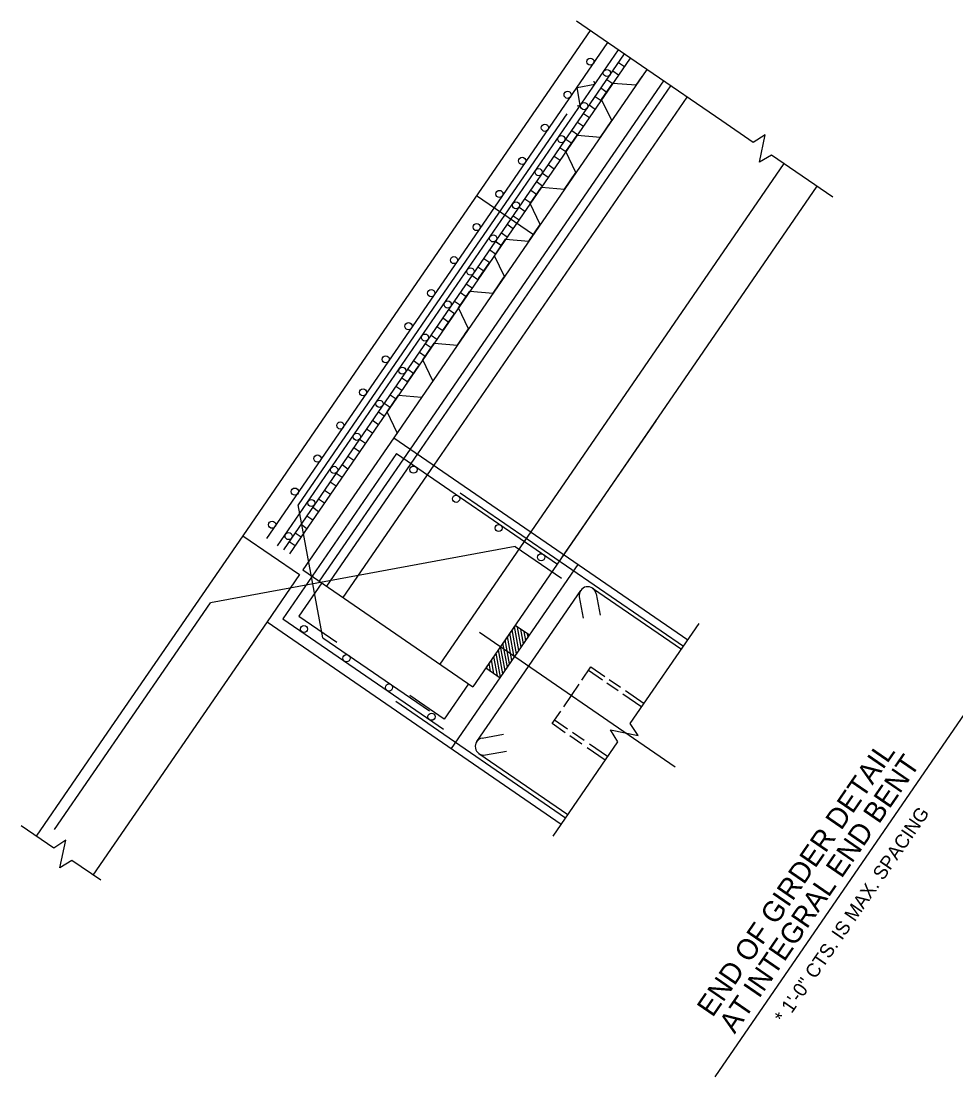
# Model space of a CAD drawing. Extents: x 2381318.4 to 2381387.3, y 332431.1 to 332503.2.
# Drawn here: x 2381332.66 to 2381346.24, y 332455.04 to 332470.39 of the extents above; entities that cross this region are included whole.
import ezdxf

# ---------------------------------------------------------------- set-up
doc = ezdxf.new("R2010")
doc.units = 0
for name, color, linetype in [('Beam Bolsters CELL', 7, 'Continuous'), ('Dimension Lines', 7, 'Continuous'), ('Dimension_Lines', 7, 'Continuous'), ('Mis Object Lines', 7, 'Continuous'), ('P_SMU_Approach_Slab', 7, 'Continuous'), ('P_SMU_BBU', 7, 'Continuous'), ('P_SMU_Deck', 7, 'Continuous'), ('P_SMU_Elastomeric Bearings', 7, 'Continuous'), ('P_SMU_End_Bent_Cap', 7, 'Continuous'), ('P_SMU_Mis_Centerline_Manual', 7, 'Continuous'), ('P_SMU_Rebar_B_Bar', 7, 'Continuous'), ('P_SMU_SIP_Metal_Formwork', 7, 'Continuous'), ('P_SMU_Steel_Pile', 7, 'Continuous'), ('Rebar Lines', 7, 'Continuous'), ('Rebar Lines CELL', 7, 'Continuous'), ('Structural Steel Lines', 7, 'Continuous'), ('Subtitle Text', 7, 'Continuous'), ('Sup Concrete Girder Lines', 7, 'Continuous'), ('Text', 7, 'Continuous')]:
    doc.layers.add(name, color=color, linetype=linetype)

msp = doc.modelspace()

# ---------------------------------------------------------------- linework, layer by layer
at = {"layer": 'Beam Bolsters CELL'}
msp.add_lwpolyline([(2381340.74, 332469.154), (2381340.785, 332469.163), (2381340.737, 332469.423), (2381340.996, 332469.47), (2381340.987, 332469.516)], dxfattribs=at)
at = {"layer": 'Dimension Lines'}
msp.add_line((2381341.882, 332464.577), (2381340.518, 332462.592), dxfattribs=at)
at = {"layer": 'Dimension_Lines'}
for p, q in [((2381341.752, 332469.684), (2381340.729, 332470.387)), ((2381342.839, 332468.936), (2381341.752, 332469.684)), ((2381343.298, 332468.621), (2381342.839, 332468.936)), ((2381343.473, 332468.735), (2381343.298, 332468.621)), ((2381343.39, 332468.334), (2381343.473, 332468.735)), ((2381343.564, 332468.438), (2381343.39, 332468.334)), ((2381344.453, 332467.828), (2381343.564, 332468.438)), ((2381341.511, 332460.175), (2381342.51, 332461.628)), ((2381341.329, 332459.909), (2381341.225, 332460.083)), ((2381341.225, 332460.083), (2381341.625, 332460)), ((2381341.625, 332460), (2381341.511, 332460.175)), ((2381340.388, 332458.54), (2381341.329, 332459.909)), ((2381333.132, 332458.366), (2381332.659, 332458.691)), ((2381333.307, 332458.48), (2381333.132, 332458.366)), ((2381333.223, 332458.079), (2381333.307, 332458.48)), ((2381333.397, 332458.183), (2381333.223, 332458.079)), ((2381333.815, 332457.897), (2381333.397, 332458.183))]:
    msp.add_line(p, q, dxfattribs=at)
at = {"layer": 'Mis Object Lines'}
msp.add_line((2381338.072, 332464.332), (2381338.073, 332464.331), dxfattribs=at)
at = {"layer": 'P_SMU_Approach_Slab'}
for p, q in [((2381335.879, 332462.906), (2381333.916, 332460.049)), ((2381336.232, 332461.653), (2381333.703, 332457.973)), ((2381333.916, 332460.049), (2381332.879, 332458.54))]:
    msp.add_line(p, q, dxfattribs=at)
at = {"layer": 'P_SMU_BBU'}
for p, q in [((2381341.424, 332469.909), (2381336.472, 332462.701)), ((2381341.51, 332469.85), (2381336.558, 332462.642)), ((2381341.341, 332469.787), (2381341.427, 332469.728)), ((2381341.256, 332469.663), (2381341.341, 332469.604)), ((2381341.085, 332469.415), (2381341.171, 332469.356)), ((2381341.095, 332469.246), (2381341.259, 332469.485)), ((2381341.17, 332469.539), (2381341.256, 332469.48)), ((2381341, 332469.291), (2381341.086, 332469.232)), ((2381340.915, 332469.168), (2381341.001, 332469.109)), ((2381340.83, 332469.044), (2381340.916, 332468.985)), ((2381340.66, 332468.796), (2381340.746, 332468.737)), ((2381340.745, 332468.92), (2381340.831, 332468.861)), ((2381340.575, 332468.672), (2381340.66, 332468.613)), ((2381340.576, 332468.489), (2381340.74, 332468.728)), ((2381340.489, 332468.548), (2381340.575, 332468.489)), ((2381340.404, 332468.424), (2381340.49, 332468.365)), ((2381340.319, 332468.3), (2381340.405, 332468.241)), ((2381340.149, 332468.053), (2381340.235, 332467.994)), ((2381340.234, 332468.177), (2381340.32, 332468.118)), ((2381340.056, 332467.733), (2381340.22, 332467.972)), ((2381340.064, 332467.929), (2381340.15, 332467.87)), ((2381339.979, 332467.805), (2381340.065, 332467.746)), ((2381339.894, 332467.681), (2381339.979, 332467.622)), ((2381339.723, 332467.433), (2381339.809, 332467.374)), ((2381339.808, 332467.557), (2381339.894, 332467.498)), ((2381339.638, 332467.309), (2381339.724, 332467.25)), ((2381339.536, 332466.977), (2381339.7, 332467.216)), ((2381339.553, 332467.186), (2381339.639, 332467.127)), ((2381339.553, 332467.185), (2381339.639, 332467.126)), ((2381339.468, 332467.062), (2381339.554, 332467.003)), ((2381339.468, 332467.062), (2381339.554, 332467.003)), ((2381339.298, 332466.814), (2381339.383, 332466.755)), ((2381339.307, 332466.644), (2381339.472, 332466.883)), ((2381339.383, 332466.938), (2381339.469, 332466.879)), ((2381339.212, 332466.69), (2381339.298, 332466.631)), ((2381339.127, 332466.566), (2381339.213, 332466.507)), ((2381339.016, 332466.22), (2381339.181, 332466.459)), ((2381339.042, 332466.442), (2381339.128, 332466.383)), ((2381338.872, 332466.194), (2381338.958, 332466.135)), ((2381338.957, 332466.318), (2381339.043, 332466.259)), ((2381338.787, 332466.071), (2381338.873, 332466.012)), ((2381338.788, 332465.888), (2381338.952, 332466.127)), ((2381338.702, 332465.947), (2381338.788, 332465.888)), ((2381338.617, 332465.823), (2381338.702, 332465.764)), ((2381338.446, 332465.575), (2381338.532, 332465.516)), ((2381338.497, 332465.464), (2381338.661, 332465.703)), ((2381338.532, 332465.699), (2381338.617, 332465.64)), ((2381338.361, 332465.451), (2381338.447, 332465.392)), ((2381338.268, 332465.132), (2381338.432, 332465.37)), ((2381338.276, 332465.327), (2381338.362, 332465.268)), ((2381338.191, 332465.203), (2381338.277, 332465.144)), ((2381338.021, 332464.956), (2381338.107, 332464.897)), ((2381338.106, 332465.079), (2381338.192, 332465.02)), ((2381337.936, 332464.832), (2381338.021, 332464.773)), ((2381337.977, 332464.708), (2381338.141, 332464.947)), ((2381337.85, 332464.708), (2381337.936, 332464.649)), ((2381337.765, 332464.584), (2381337.851, 332464.525)), ((2381337.68, 332464.46), (2381337.766, 332464.401)), ((2381337.577, 332464.31), (2381337.663, 332464.251)), ((2381337.407, 332464.063), (2381337.493, 332464.004)), ((2381337.492, 332464.187), (2381337.578, 332464.128)), ((2381337.322, 332463.939), (2381337.408, 332463.88)), ((2381337.237, 332463.815), (2381337.323, 332463.756)), ((2381337.152, 332463.691), (2381337.238, 332463.632)), ((2381336.982, 332463.443), (2381337.067, 332463.384)), ((2381337.067, 332463.567), (2381337.153, 332463.508)), ((2381336.896, 332463.319), (2381336.982, 332463.26)), ((2381336.811, 332463.196), (2381336.897, 332463.136)), ((2381336.726, 332463.072), (2381336.812, 332463.013)), ((2381336.556, 332462.824), (2381336.642, 332462.765)), ((2381336.641, 332462.948), (2381336.727, 332462.889))]:
    msp.add_line(p, q, dxfattribs=at)
at = {"layer": 'P_SMU_Deck'}
for p, q in [((2381340.927, 332470.252), (2381336.979, 332464.507)), ((2381339.277, 332467.851), (2381340.103, 332467.284)), ((2381336.979, 332464.507), (2381335.879, 332462.906)), ((2381335.879, 332462.906), (2381336.704, 332462.34))]:
    msp.add_line(p, q, dxfattribs=at)
at = {"layer": 'P_SMU_Elastomeric Bearings'}
for p, q in [((2381339.892, 332461.239), (2381339.827, 332461.587)), ((2381339.925, 332461.288), (2381339.871, 332461.579)), ((2381339.792, 332461.093), (2381339.727, 332461.441)), ((2381339.825, 332461.142), (2381339.761, 332461.489)), ((2381339.858, 332461.19), (2381339.794, 332461.538)), ((2381339.959, 332461.336), (2381339.92, 332461.546)), ((2381339.992, 332461.385), (2381339.968, 332461.512)), ((2381340.025, 332461.433), (2381340.017, 332461.479)), ((2381339.692, 332460.948), (2381339.627, 332461.295)), ((2381339.725, 332460.996), (2381339.661, 332461.344)), ((2381339.758, 332461.045), (2381339.694, 332461.392)), ((2381339.579, 332460.87), (2381339.527, 332461.149)), ((2381339.625, 332460.85), (2381339.56, 332461.198)), ((2381339.658, 332460.899), (2381339.594, 332461.247)), ((2381339.433, 332460.97), (2381339.427, 332461.004)), ((2381339.482, 332460.936), (2381339.46, 332461.052)), ((2381339.53, 332460.903), (2381339.494, 332461.101))]:
    msp.add_line(p, q, dxfattribs=at)
msp.add_lwpolyline([(2381339.619, 332460.842), (2381340.044, 332461.46), (2381339.838, 332461.602), (2381339.413, 332460.984)], close=True, dxfattribs=at)
at = {"layer": 'P_SMU_End_Bent_Cap'}
for p, q in [((2381338.073, 332464.331), (2381342.349, 332461.393)), ((2381338.911, 332459.812), (2381340.752, 332462.49)), ((2381336.704, 332462.34), (2381336.232, 332461.653)), ((2381336.232, 332461.653), (2381340.508, 332458.715))]:
    msp.add_line(p, q, dxfattribs=at)
at = {"layer": 'P_SMU_Mis_Centerline_Manual'}
msp.add_line((2381339.32, 332461.503), (2381342.164, 332459.548), dxfattribs=at)
at = {"layer": 'P_SMU_Rebar_B_Bar'}
for p, q in [((2381339.148, 332467.111), (2381341.185, 332470.075)), ((2381336.386, 332462.76), (2381341.339, 332469.969)), ((2381338.611, 332466.329), (2381339.148, 332467.111)), ((2381337.127, 332464.17), (2381338.611, 332466.329)), ((2381336.231, 332462.867), (2381337.127, 332464.17))]:
    msp.add_line(p, q, dxfattribs=at)
at = {"layer": 'P_SMU_SIP_Metal_Formwork'}
for p, q in [((2381341.259, 332469.485), (2381341.596, 332469.458)), ((2381341.241, 332468.94), (2381341.095, 332469.246)), ((2381340.74, 332468.728), (2381341.077, 332468.702)), ((2381340.721, 332468.184), (2381340.576, 332468.489)), ((2381340.22, 332467.972), (2381340.557, 332467.945)), ((2381340.201, 332467.428), (2381340.056, 332467.733)), ((2381339.7, 332467.216), (2381340.037, 332467.189)), ((2381339.682, 332466.672), (2381339.536, 332466.977)), ((2381339.181, 332466.459), (2381339.518, 332466.433)), ((2381339.162, 332465.915), (2381339.016, 332466.22)), ((2381338.661, 332465.703), (2381338.998, 332465.676)), ((2381338.642, 332465.159), (2381338.497, 332465.464)), ((2381338.141, 332464.947), (2381338.478, 332464.92)), ((2381338.122, 332464.403), (2381337.977, 332464.708))]:
    msp.add_line(p, q, dxfattribs=at)
at = {"layer": 'P_SMU_Steel_Pile'}
for p, q in [((2381341.108, 332460.807), (2381340.905, 332460.947)), ((2381341.334, 332460.652), (2381341.17, 332460.764)), ((2381341.677, 332460.416), (2381341.405, 332460.603)), ((2381340.601, 332460.093), (2381340.409, 332460.226)), ((2381340.841, 332459.929), (2381340.67, 332460.047)), ((2381341.182, 332459.695), (2381340.92, 332459.875))]:
    msp.add_line(p, q, dxfattribs=at)
for points in [[(2381340.808, 332460.807), (2381340.94, 332460.998), (2381341.143, 332460.859)], [(2381341.206, 332460.816), (2381341.369, 332460.703)], [(2381340.543, 332460.42), (2381340.769, 332460.749)], [(2381341.44, 332460.655), (2381341.713, 332460.468)], [(2381340.566, 332460.042), (2381340.374, 332460.174), (2381340.5, 332460.358)], [(2381340.805, 332459.877), (2381340.634, 332459.995)], [(2381341.146, 332459.643), (2381340.884, 332459.823)]]:
    msp.add_lwpolyline(points, dxfattribs=at)
at = {"layer": 'Rebar Lines'}
for p, q in [((2381340.588, 332469.038), (2381338.701, 332466.292)), ((2381338.701, 332466.292), (2381337.202, 332464.11)), ((2381338.115, 332464.1), (2381336.464, 332461.696)), ((2381337.202, 332464.11), (2381336.685, 332463.357)), ((2381338.115, 332464.1), (2381340.451, 332462.494)), ((2381339.04, 332463.531), (2381342.286, 332461.302)), ((2381337.043, 332461.424), (2381336.685, 332463.357)), ((2381339.836, 332462.751), (2381335.411, 332461.931)), ((2381339.836, 332462.751), (2381340.51, 332462.287)), ((2381337.027, 332462.219), (2381336.696, 332461.738)), ((2381339.28, 332459.913), (2381340.79, 332462.11)), ((2381340.964, 332462.143), (2381342.254, 332461.256)), ((2381341.016, 332462.062), (2381341.073, 332461.751)), ((2381333.146, 332458.634), (2381335.411, 332461.931)), ((2381340.77, 332462.017), (2381340.828, 332461.706)), ((2381336.696, 332461.738), (2381337.246, 332461.361)), ((2381336.464, 332461.696), (2381338.795, 332460.094)), ((2381337.043, 332461.424), (2381338.593, 332460.359)), ((2381339.162, 332460.752), (2381338.808, 332460.237)), ((2381338.808, 332460.237), (2381338.306, 332460.582)), ((2381338.103, 332460.502), (2381340.571, 332458.806)), ((2381339.36, 332459.965), (2381339.668, 332460.022)), ((2381339.312, 332459.739), (2381340.602, 332458.852)), ((2381339.405, 332459.719), (2381339.714, 332459.776))]:
    msp.add_line(p, q, dxfattribs=at)
for centre, start, end in [((2381340.893, 332462.04), 10.5048, 190.5046), ((2381339.383, 332459.842), 100.5046, 280.5045)]:
    msp.add_arc(centre, 0.125, start, end, dxfattribs=at)
at = {"layer": 'Rebar Lines CELL'}
for centre in [(2381340.931, 332469.797), (2381341.171, 332469.632), (2381340.6, 332469.316), (2381340.841, 332469.151), (2381340.27, 332468.836), (2381340.51, 332468.671), (2381339.94, 332468.355), (2381340.18, 332468.19), (2381339.609, 332467.874), (2381339.85, 332467.709), (2381339.279, 332467.393), (2381339.519, 332467.228), (2381338.949, 332466.913), (2381339.189, 332466.747), (2381338.618, 332466.432), (2381338.858, 332466.267), (2381338.288, 332465.951), (2381338.528, 332465.786), (2381337.957, 332465.47), (2381338.198, 332465.305), (2381337.627, 332464.99), (2381337.867, 332464.824), (2381337.297, 332464.509), (2381337.537, 332464.344), (2381336.966, 332464.028), (2381337.207, 332463.863), (2381338.361, 332463.867), (2381336.636, 332463.547), (2381336.876, 332463.382), (2381338.98, 332463.443), (2381336.306, 332463.066), (2381339.598, 332463.018), (2381336.546, 332462.901), (2381340.216, 332462.593), (2381336.769, 332461.55), (2381337.387, 332461.125), (2381338.005, 332460.7), (2381338.623, 332460.275)]:
    msp.add_circle(centre, 0.0521, dxfattribs=at)
at = {"layer": 'Structural Steel Lines'}
for p, q in [((2381341.595, 332469.455), (2381341.682, 332469.582)), ((2381341.077, 332468.702), (2381341.241, 332468.94)), ((2381340.557, 332467.945), (2381340.721, 332468.184)), ((2381340.037, 332467.189), (2381340.201, 332467.428)), ((2381339.518, 332466.433), (2381339.682, 332466.672)), ((2381339.627, 332466.592), (2381339.682, 332466.672)), ((2381338.998, 332465.676), (2381339.162, 332465.915)), ((2381339.107, 332465.836), (2381339.162, 332465.915))]:
    msp.add_line(p, q, dxfattribs=at)
at = {"layer": 'Subtitle Text'}
msp.add_line((2381342.744, 332455.039), (2381346.676, 332460.762), dxfattribs=at)
at = {"layer": 'Sup Concrete Girder Lines'}
for p, q in [((2381341.752, 332469.684), (2381338.824, 332465.423)), ((2381341.992, 332469.519), (2381338.314, 332464.166)), ((2381342.095, 332469.448), (2381338.417, 332464.095)), ((2381342.335, 332469.283), (2381338.657, 332463.93)), ((2381343.743, 332468.315), (2381340.065, 332462.962)), ((2381344.224, 332467.985), (2381340.546, 332462.632)), ((2381338.824, 332465.423), (2381338.073, 332464.331)), ((2381338.073, 332464.331), (2381336.752, 332462.408)), ((2381338.314, 332464.166), (2381336.992, 332462.243)), ((2381338.417, 332464.095), (2381337.095, 332462.172)), ((2381338.657, 332463.93), (2381337.336, 332462.007)), ((2381340.065, 332462.962), (2381338.744, 332461.039)), ((2381340.546, 332462.632), (2381339.224, 332460.709)), ((2381336.752, 332462.408), (2381339.224, 332460.709))]:
    msp.add_line(p, q, dxfattribs=at)

# ---------------------------------------------------------------- texts
at = {"layer": 'Subtitle Text'}
for s, p in [('END OF GIRDER DETAIL', (2381342.707, 332455.893)), ('AT INTEGRAL END BENT', (2381343.028, 332455.654))]:
    msp.add_text(s, height=0.3, rotation=55.5046, dxfattribs=at).set_placement(p)
at = {"layer": 'Text'}
msp.add_text('* 1\'-0" CTS. IS MAX. SPACING', height=0.2, rotation=55.5046, dxfattribs=at).set_placement((2381343.755, 332455.804))

doc.saveas('drawing.dxf')
